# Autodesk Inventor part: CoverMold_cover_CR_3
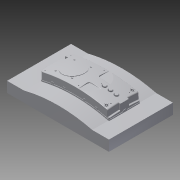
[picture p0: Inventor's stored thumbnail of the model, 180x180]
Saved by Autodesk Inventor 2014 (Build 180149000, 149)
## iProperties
Created: 2009-12
Part Number: CoverMold_cover_CR_3
Document SubType Name: Modeling
Designer: gaom
Density: 1 g/cm^3
Material: Generic
Appearance: Default
Author: gaom
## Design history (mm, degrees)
node "CoverMold_cover_CR_Base"
feature "Solid1::CoverMold_cover_CR_Base"
tag "TaggingFeature1"
body "Solid1"
